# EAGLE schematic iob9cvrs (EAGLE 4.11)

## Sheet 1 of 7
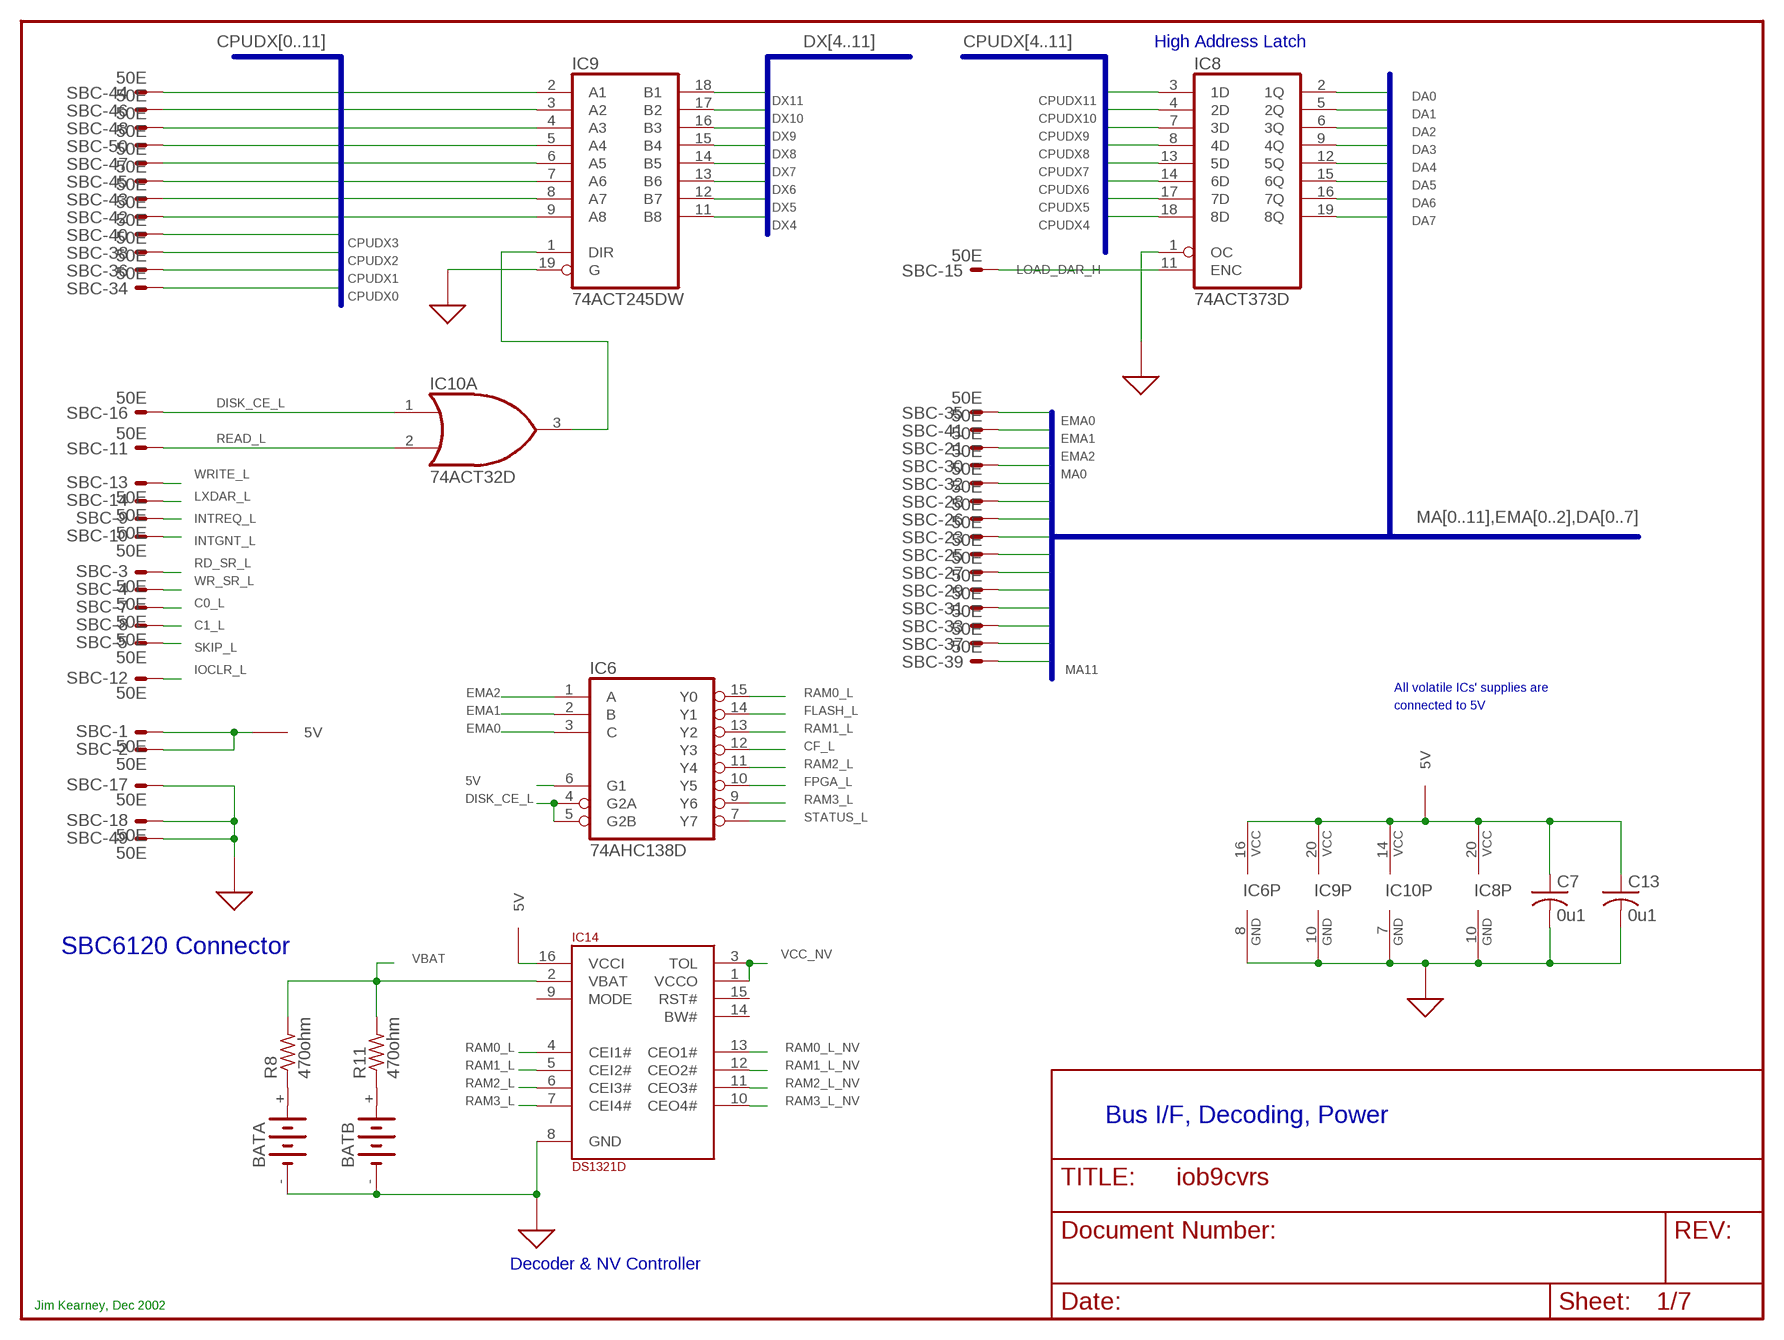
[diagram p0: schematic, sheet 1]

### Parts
BATA  CR2032HOLDER  [CR2032HOLDER]
BATB  CR2032HOLDER  [CR2032HOLDER]
C7  0u1  C-USC0805  [C0805]
C13  0u1  C-USC0805  [C0805]
IC6  74AHC138D  74LS138D  [SO16]
IC8  74ACT373D  74LS373DW  [SO20W]
IC9  74ACT245DW  74LS245DW  [SO20W]
IC10  74ACT32D  74LS32D  [SO14]
IC14  DS1321D  [SO16]
R8  470ohm  R-US_M0805  [M0805]
R11  470ohm  R-US_M0805  [M0805]
SBC  50E  ML50E  [ML50]

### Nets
5V [power]: C7.1 C13.1 IC6.6(G1) IC6.16(VCC) IC8.20(VCC) IC9.20(VCC) IC10.14(P:VCC) IC14.16(VCCI) SBC.1 SBC.2 ; also sheet 2,3,4,5,6
C0_L: SBC.7 ; also sheet 4
C1_L: SBC.8 ; also sheet 4
CF_L: IC6.12(Y3) ; also sheet 3
CPUDX0: SBC.34 ; also sheet 4,5
CPUDX1: SBC.36 ; also sheet 4,5
CPUDX2: SBC.38 ; also sheet 4,5
CPUDX3: SBC.40 ; also sheet 4,5
CPUDX4: IC8.18(8D) IC9.9(A8) SBC.42 ; also sheet 3,5
CPUDX5: IC8.17(7D) IC9.8(A7) SBC.43 ; also sheet 3,5
CPUDX6: IC8.14(6D) IC9.7(A6) SBC.45 ; also sheet 3,5
CPUDX7: IC8.13(5D) IC9.6(A5) SBC.47 ; also sheet 3,5
CPUDX8: IC8.8(4D) IC9.5(A4) SBC.50 ; also sheet 3,5
CPUDX9: IC8.7(3D) IC9.4(A3) SBC.48 ; also sheet 3,5
CPUDX10: IC8.4(2D) IC9.3(A2) SBC.46 ; also sheet 3,5
CPUDX11: IC8.3(1D) IC9.2(A1) SBC.44 ; also sheet 3,5
DA0: IC8.2(1Q) ; also sheet 2
DA1: IC8.5(2Q) ; also sheet 2
DA2: IC8.6(3Q) ; also sheet 2
DA3: IC8.9(4Q) ; also sheet 2
DA4: IC8.12(5Q) ; also sheet 2
DA5: IC8.15(6Q) ; also sheet 2
DA6: IC8.16(7Q) ; also sheet 2
DA7: IC8.19(8Q)
DISK_CE_L: IC6.4(G2A) IC6.5(G2B) IC10.1(A:I0) SBC.16
DX4: IC9.11(B8) ; also sheet 2,3
DX5: IC9.12(B7) ; also sheet 2,3
DX6: IC9.13(B6) ; also sheet 2,3
DX7: IC9.14(B5) ; also sheet 2,3
DX8: IC9.15(B4) ; also sheet 2,3
DX9: IC9.16(B3) ; also sheet 2,3
DX10: IC9.17(B2) ; also sheet 2,3
DX11: IC9.18(B1) ; also sheet 2,3
EMA0: IC6.3(C) SBC.35
EMA1: IC6.2(B) SBC.41
EMA2: IC6.1(A) SBC.21
FLASH_L: IC6.14(Y1) ; also sheet 2
FPGA_L: IC6.10(Y5) ; also sheet 3
GND [gnd]: BATA.- BATB.- C7.2 C13.2 IC6.8(GND) IC8.1(OC) IC8.10(GND) IC9.10(GND) IC9.19(G) IC10.7(P:GND) IC14.8(GND) SBC.17 SBC.18 SBC.49 ; also sheet 2,3,4,5,6,7
INTGNT_L: SBC.10 ; also sheet 4
INTREQ_L: SBC.9 ; also sheet 4
IOCLR_L: SBC.12 ; also sheet 2,4
LOAD_DAR_H: IC8.11(ENC) SBC.15
LXDAR_L: SBC.14 ; also sheet 4
MA0: SBC.30 ; also sheet 2
MA1: SBC.32 ; also sheet 2
MA2: SBC.28 ; also sheet 2
MA3: SBC.26 ; also sheet 2
MA4: SBC.23 ; also sheet 2
MA5: SBC.25 ; also sheet 2
MA6: SBC.27 ; also sheet 2
MA7: SBC.29 ; also sheet 2
MA8: SBC.31 ; also sheet 2
MA9: SBC.33 ; also sheet 2,3
MA10: SBC.37 ; also sheet 2,3
MA11: SBC.39 ; also sheet 2,3
N$2: BATA.+ R8.1
N$11: BATB.+ R11.1
N$91: IC9.1(DIR) IC10.3(A:O)
RAM0_L: IC6.15(Y0) IC14.4(CEI1#)
RAM0_L_NV: IC14.13(CEO1#) ; also sheet 2
RAM1_L: IC6.13(Y2) IC14.5(CEI2#)
RAM1_L_NV: IC14.12(CEO2#) ; also sheet 2
RAM2_L: IC6.11(Y4) IC14.6(CEI3#)
RAM2_L_NV: IC14.11(CEO3#) ; also sheet 2
RAM3_L: IC6.9(Y6) IC14.7(CEI4#)
RAM3_L_NV: IC14.10(CEO4#) ; also sheet 2
RD_SR_L: SBC.3 ; also sheet 4
READ_L: IC10.2(A:I1) SBC.11 ; also sheet 2,3,4
SKIP_L: SBC.5 ; also sheet 4
STATUS_L: IC6.7(Y7) ; also sheet 3
VBAT: IC14.2(VBAT) R8.2 R11.2 ; also sheet 6
VCC_NV [power]: IC14.1(VCCO) IC14.3(TOL) ; also sheet 2
WR_SR_L: SBC.4 ; also sheet 4
WRITE_L: SBC.13 ; also sheet 2,3,4
Unconnected: IC14.9(MODE) IC14.14(BW#) IC14.15(RST#) SBC.6 SBC.19 SBC.20 SBC.22 SBC.24

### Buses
DX[4..11]
MA[0..11],EMA[0..2],DA[0..7]
CPUDX[0..11]
CPUDX[4..11]

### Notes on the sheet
- High Address Latch
- All volatile ICs' supplies are
- connected to 5V
- SBC6120 Connector
- Bus I/F, Decoding, Power
- Decoder & NV Controller
- Jim Kearney, Dec 2002

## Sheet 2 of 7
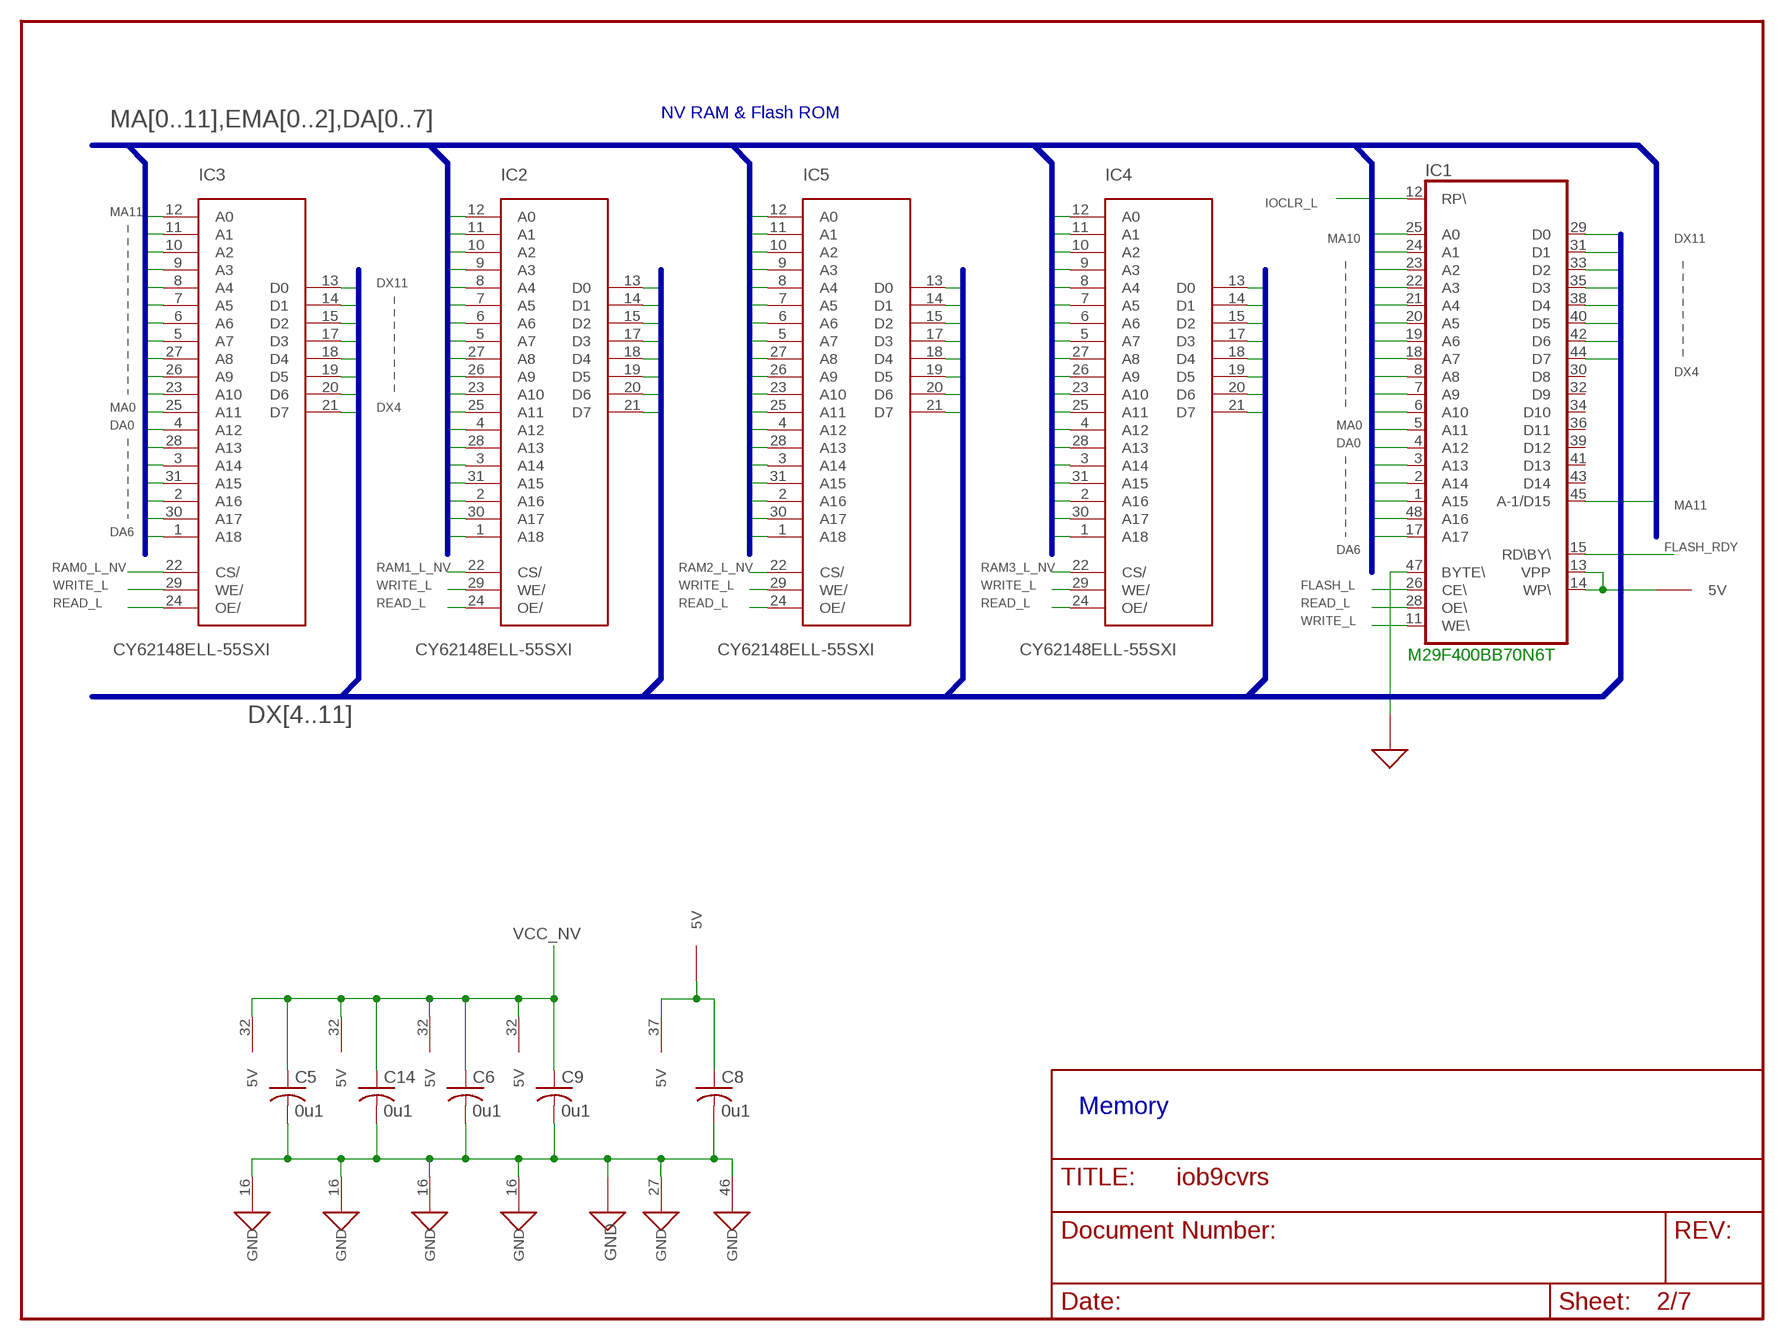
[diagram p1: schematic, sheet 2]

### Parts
C5  0u1  C-USC0805  [C0805]
C6  0u1  C-USC0805  [C0805]
C8  0u1  C-USC0805  [C0805]
C9  0u1  C-USC0805  [C0805]
C14  0u1  C-USC0805  [C0805]
IC1  M29F400BB70N6T  LH28F400  [TSOP48]
IC2  CY62148ELL-55SXI  TC554001AF  [SOP32]
IC3  CY62148ELL-55SXI  TC554001AF  [SOP32]
IC4  CY62148ELL-55SXI  TC554001AF  [SOP32]
IC5  CY62148ELL-55SXI  TC554001AF  [SOP32]

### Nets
5V [power]: C8.1 IC1.13(VPP) IC1.14(WP\) IC1.37(5V) ; also sheet 1,3,4,5,6
DA0: IC1.5(A11) IC2.4(A12) IC3.4(A12) IC4.4(A12) IC5.4(A12) ; also sheet 1
DA1: IC1.4(A12) IC2.28(A13) IC3.28(A13) IC4.28(A13) IC5.28(A13) ; also sheet 1
DA2: IC1.3(A13) IC2.3(A14) IC3.3(A14) IC4.3(A14) IC5.3(A14) ; also sheet 1
DA3: IC1.2(A14) IC2.31(A15) IC3.31(A15) IC4.31(A15) IC5.31(A15) ; also sheet 1
DA4: IC1.1(A15) IC2.2(A16) IC3.2(A16) IC4.2(A16) IC5.2(A16) ; also sheet 1
DA5: IC1.48(A16) IC2.30(A17) IC3.30(A17) IC4.30(A17) IC5.30(A17) ; also sheet 1
DA6: IC1.17(A17) IC2.1(A18) IC3.1(A18) IC4.1(A18) IC5.1(A18) ; also sheet 1
DX4: IC1.44(D7) IC2.21(D7) IC3.21(D7) IC4.21(D7) IC5.21(D7) ; also sheet 1,3
DX5: IC1.42(D6) IC2.20(D6) IC3.20(D6) IC4.20(D6) IC5.20(D6) ; also sheet 1,3
DX6: IC1.40(D5) IC2.19(D5) IC3.19(D5) IC4.19(D5) IC5.19(D5) ; also sheet 1,3
DX7: IC1.38(D4) IC2.18(D4) IC3.18(D4) IC4.18(D4) IC5.18(D4) ; also sheet 1,3
DX8: IC1.35(D3) IC2.17(D3) IC3.17(D3) IC4.17(D3) IC5.17(D3) ; also sheet 1,3
DX9: IC1.33(D2) IC2.15(D2) IC3.15(D2) IC4.15(D2) IC5.15(D2) ; also sheet 1,3
DX10: IC1.31(D1) IC2.14(D1) IC3.14(D1) IC4.14(D1) IC5.14(D1) ; also sheet 1,3
DX11: IC1.29(D0) IC2.13(D0) IC3.13(D0) IC4.13(D0) IC5.13(D0) ; also sheet 1,3
FLASH_L: IC1.26(CE\) ; also sheet 1
FLASH_RDY: IC1.15(RD\BY\) ; also sheet 3
GND [gnd]: C5.2 C6.2 C8.2 C9.2 C14.2 IC1.27(GND) IC1.46(GND) IC1.47(BYTE\) IC2.16(GND) IC3.16(GND) IC4.16(GND) IC5.16(GND) ; also sheet 1,3,4,5,6,7
IOCLR_L: IC1.12(RP\) ; also sheet 1,4
MA0: IC1.6(A10) IC2.25(A11) IC3.25(A11) IC4.25(A11) IC5.25(A11) ; also sheet 1
MA1: IC1.7(A9) IC2.23(A10) IC3.23(A10) IC4.23(A10) IC5.23(A10) ; also sheet 1
MA2: IC1.8(A8) IC2.26(A9) IC3.26(A9) IC4.26(A9) IC5.26(A9) ; also sheet 1
MA3: IC1.18(A7) IC2.27(A8) IC3.27(A8) IC4.27(A8) IC5.27(A8) ; also sheet 1
MA4: IC1.19(A6) IC2.5(A7) IC3.5(A7) IC4.5(A7) IC5.5(A7) ; also sheet 1
MA5: IC1.20(A5) IC2.6(A6) IC3.6(A6) IC4.6(A6) IC5.6(A6) ; also sheet 1
MA6: IC1.21(A4) IC2.7(A5) IC3.7(A5) IC4.7(A5) IC5.7(A5) ; also sheet 1
MA7: IC1.22(A3) IC2.8(A4) IC3.8(A4) IC4.8(A4) IC5.8(A4) ; also sheet 1
MA8: IC1.23(A2) IC2.9(A3) IC3.9(A3) IC4.9(A3) IC5.9(A3) ; also sheet 1
MA9: IC1.24(A1) IC2.10(A2) IC3.10(A2) IC4.10(A2) IC5.10(A2) ; also sheet 1,3
MA10: IC1.25(A0) IC2.11(A1) IC3.11(A1) IC4.11(A1) IC5.11(A1) ; also sheet 1,3
MA11: IC1.45(A-1/D15) IC2.12(A0) IC3.12(A0) IC4.12(A0) IC5.12(A0) ; also sheet 1,3
RAM0_L_NV: IC3.22(CS/) ; also sheet 1
RAM1_L_NV: IC2.22(CS/) ; also sheet 1
RAM2_L_NV: IC5.22(CS/) ; also sheet 1
RAM3_L_NV: IC4.22(CS/) ; also sheet 1
READ_L: IC1.28(OE\) IC2.24(OE/) IC3.24(OE/) IC4.24(OE/) IC5.24(OE/) ; also sheet 1,3,4
VCC_NV [power]: C5.1 C6.1 C9.1 C14.1 IC2.32(5V) IC3.32(5V) IC4.32(5V) IC5.32(5V) ; also sheet 1
WRITE_L: IC1.11(WE\) IC2.29(WE/) IC3.29(WE/) IC4.29(WE/) IC5.29(WE/) ; also sheet 1,3,4
Unconnected: IC1.30(D8) IC1.32(D9) IC1.34(D10) IC1.36(D11) IC1.39(D12) IC1.41(D13) IC1.43(D14)

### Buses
MA[0..11],EMA[0..2],DA[0..7]
DX[4..11]

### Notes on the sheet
- NV RAM & Flash ROM
- M29F400BB70N6T
- Memory

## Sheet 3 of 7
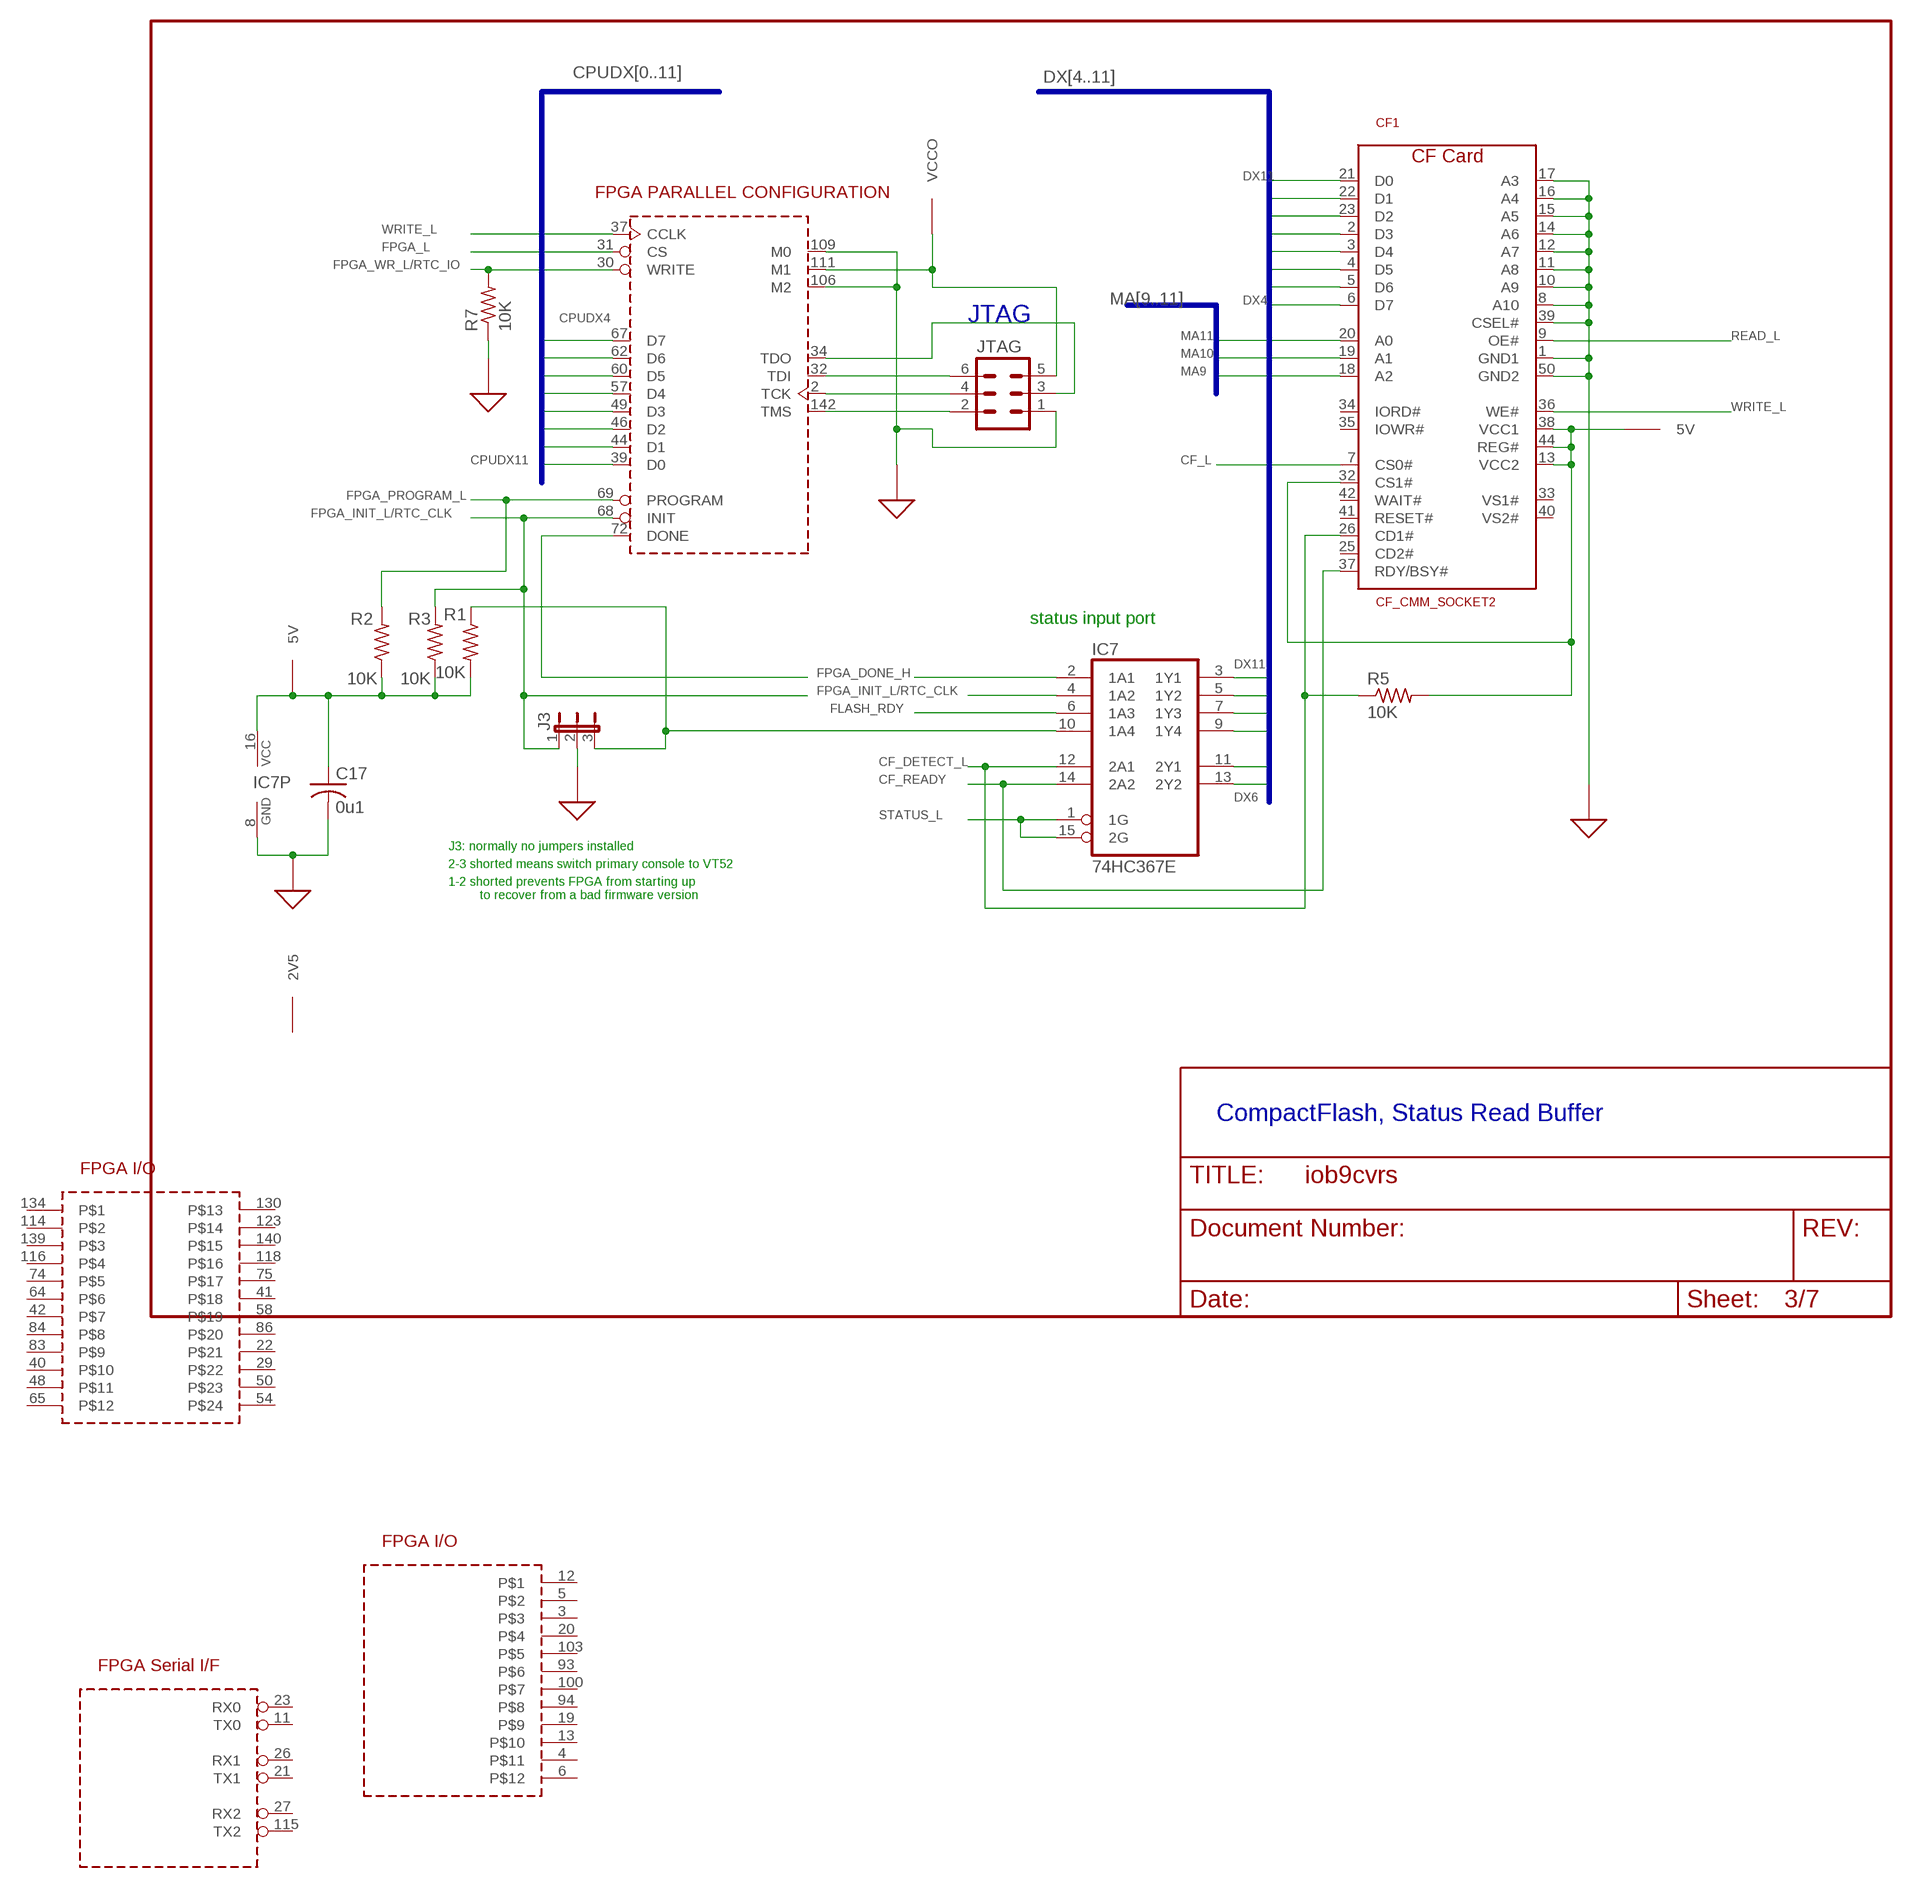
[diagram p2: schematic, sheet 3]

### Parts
C17  0u1  C-USC0805  [C0805]
CF1  CF_CMM_SOCKET2  [CF_SOCKET2_SMT]
IC7  74HC367E  74HCT367E  [SOP16]
IC12  XC2S100-5TQG144C  XC2S30-IOB1-5TQ144  [TQFP144]
J3  JP2E  [JP2]
JTAG  MA03-2  [MA03-2]
R1  10K  R-US_M0805  [M0805]
R2  10K  R-US_M0805  [M0805]
R3  10K  R-US_M0805  [M0805]
R5  10K  R-US_R0805  [R0805]
R7  10K  R-US_M0805  [M0805]

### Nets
5V [power]: C17.1 CF1.13(VCC2) CF1.32(CS1#) CF1.38(VCC1) CF1.44(REG#) IC7.16(VCC) R1.2 R2.1 R3.1 R5.2 ; also sheet 1,2,4,5,6
CF_DETECT_L: CF1.26(CD1#) IC7.12(2A1) R5.1
CF_L: CF1.7(CS0#) ; also sheet 1
CF_READY: CF1.37(RDY/BSY#) IC7.14(2A2)
CPUDX4: IC12.67(D7) ; also sheet 1,5
CPUDX5: IC12.62(D6) ; also sheet 1,5
CPUDX6: IC12.60(D5) ; also sheet 1,5
CPUDX7: IC12.57(D4) ; also sheet 1,5
CPUDX8: IC12.49(D3) ; also sheet 1,5
CPUDX9: IC12.46(D2) ; also sheet 1,5
CPUDX10: IC12.44(D1) ; also sheet 1,5
CPUDX11: IC12.39(D0) ; also sheet 1,5
DX4: CF1.6(D7) ; also sheet 1,2
DX5: CF1.5(D6) ; also sheet 1,2
DX6: CF1.4(D5) IC7.13(2Y2) ; also sheet 1,2
DX7: CF1.3(D4) IC7.11(2Y1) ; also sheet 1,2
DX8: CF1.2(D3) IC7.9(1Y4) ; also sheet 1,2
DX9: CF1.23(D2) IC7.7(1Y3) ; also sheet 1,2
DX10: CF1.22(D1) IC7.5(1Y2) ; also sheet 1,2
DX11: CF1.21(D0) IC7.3(1Y1) ; also sheet 1,2
FLASH_RDY: IC7.6(1A3) ; also sheet 2
FPGA_DONE_H: IC7.2(1A1) IC12.72(DONE)
FPGA_INIT_L/RTC_CLK: IC7.4(1A2) IC12.68(INIT) J3.1 R3.2 ; also sheet 6
FPGA_L: IC12.31(CS) ; also sheet 1
FPGA_PROGRAM_L: IC12.69(PROGRAM) R2.2 ; also sheet 4
FPGA_WR_L/RTC_IO: IC12.30(WRITE) R7.2 ; also sheet 6
GND [gnd]: C17.2 CF1.1(GND1) CF1.8(A10) CF1.10(A9) CF1.11(A8) CF1.12(A7) CF1.14(A6) CF1.15(A5) CF1.16(A4) CF1.17(A3) CF1.39(CSEL#) CF1.50(GND2) IC7.8(GND) IC12.106(M2) IC12.109(M0) J3.2 JTAG.1 R7.1 ; also sheet 1,2,4,5,6,7
MA9: CF1.18(A2) ; also sheet 1,2
MA10: CF1.19(A1) ; also sheet 1,2
MA11: CF1.20(A0) ; also sheet 1,2
N$3: IC7.10(1A4) J3.3 R1.1
READ_L: CF1.9(OE#) ; also sheet 1,2,4
STATUS_L: IC7.1(1G) IC7.15(2G) ; also sheet 1
TCK: IC12.2(TCK) JTAG.4
TDI: IC12.32(TDI) JTAG.6
TDO: IC12.34(TDO) JTAG.3
TMS: IC12.142(TMS) JTAG.2
VCCO [power2]: IC12.111(M1) JTAG.5 ; also sheet 4
WRITE_L: CF1.36(WE#) IC12.37(CCLK) ; also sheet 1,2,4
Unconnected: CF1.25(CD2#) CF1.33(VS1#) CF1.34(IORD#) CF1.35(IOWR#) CF1.40(VS2#) CF1.41(RESET#) CF1.42(WAIT#)

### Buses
DX[4..11]
MA[9..11]
CPUDX[0..11]

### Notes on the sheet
- JTAG
- status input port
- J3: normally no jumpers installed
- 2-3 shorted means switch primary console to VT52
- 1-2 shorted prevents FPGA from starting up
- to recover from a bad firmware version
- CompactFlash, Status Read Buffer

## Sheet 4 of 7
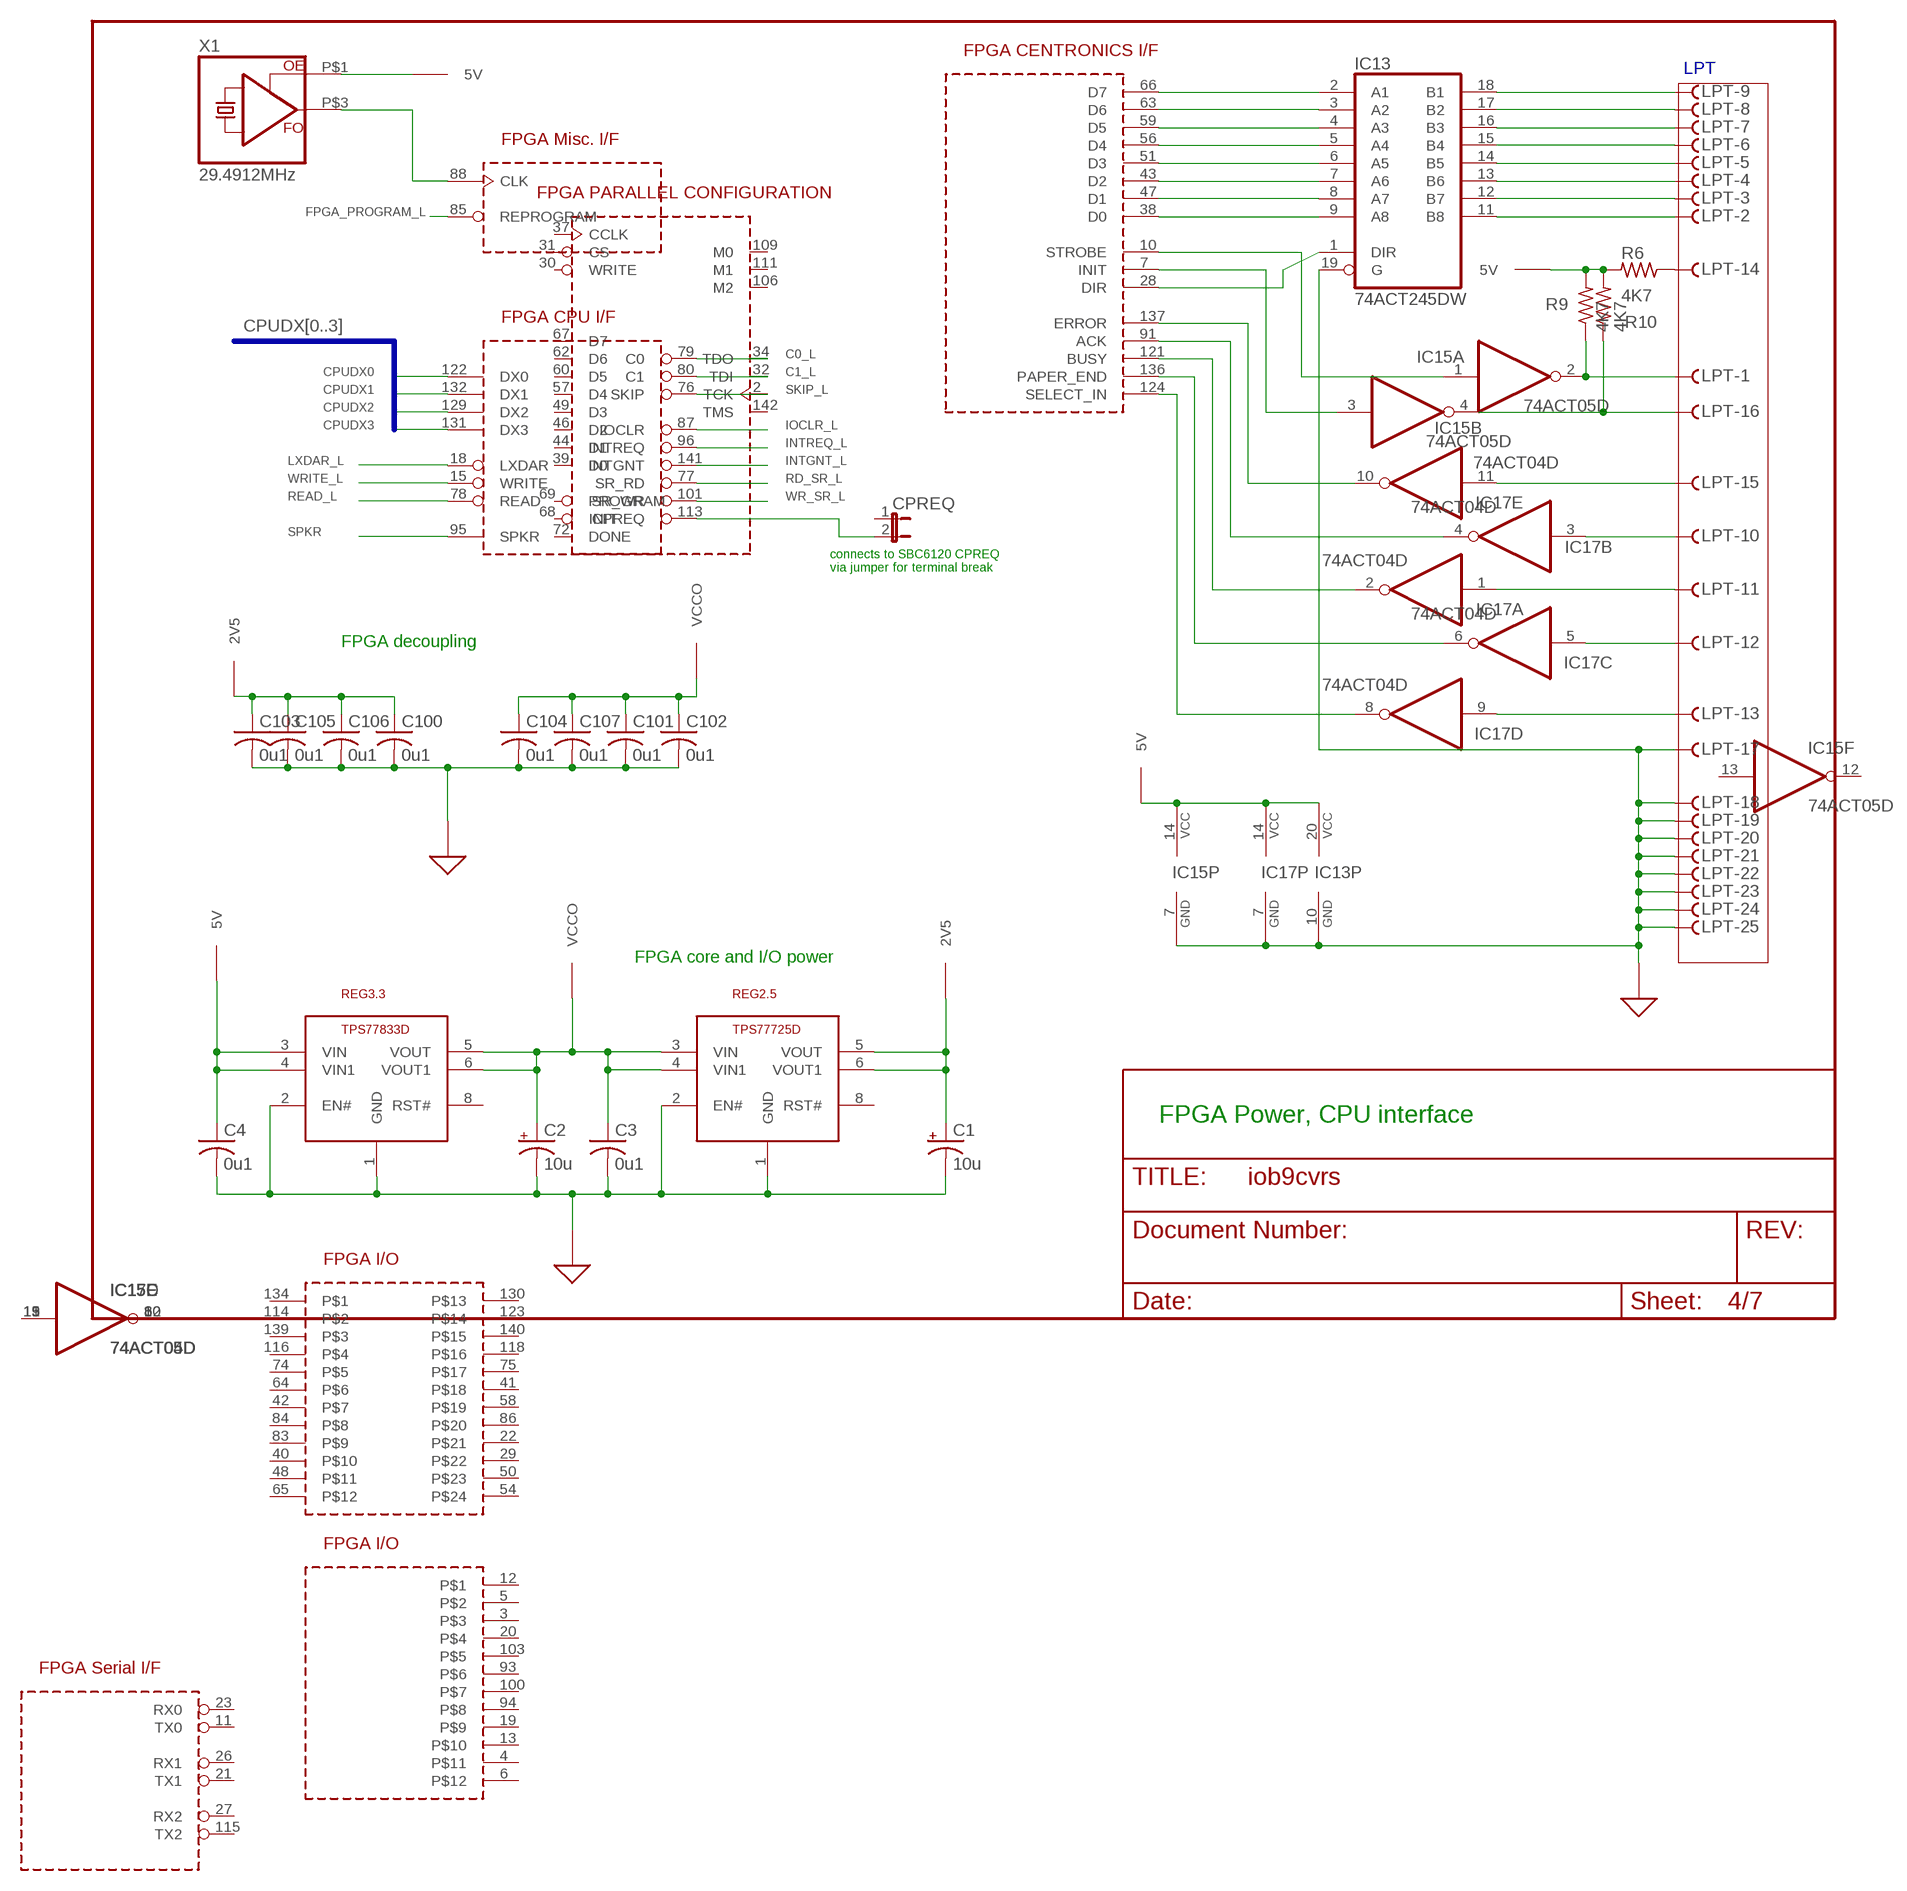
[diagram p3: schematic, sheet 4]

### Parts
C1  10u  CPOL-USD/7343-31W  [D/7343-31W]
C2  10u  CPOL-USD/7343-31W  [D/7343-31W]
C3  0u1  C-USC0805  [C0805]
C4  0u1  C-USC0805  [C0805]
C100  0u1  C-USC0805  [C0805]
C101  0u1  C-USC0805  [C0805]
C102  0u1  C-USC0805  [C0805]
C103  0u1  C-USC0805  [C0805]
C104  0u1  C-USC0805  [C0805]
C105  0u1  C-USC0805  [C0805]
C106  0u1  C-USC0805  [C0805]
C107  0u1  C-USC0805  [C0805]
CPREQ  JP1E  [JP1]
IC13  74ACT245DW  74LS245DW  [SO20W]
IC15  74ACT05D  74ALS05D  [SO14]
IC17  74ACT04D  74ALS04D  [SO14]
LPT  F25HS  [F25H]
R6  4K7  R-US_M0805  [M0805]
R9  4K7  R-US_M0805  [M0805]
R10  4K7  R-US_M0805  [M0805]
REG2.5  TPS77725D  TPS77XXXD  [SO08]
REG3.3  TPS77833D  TPS77XXXD  [SO08]
X1  29.4912MHz  OSC-OE-5V  [SG636]

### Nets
2V5 [power2]: C1.+ C100.1 C103.1 C105.1 C106.1 REG2.5.5(VOUT) REG2.5.6(VOUT1)
5V [power]: C4.1 IC13.20(VCC) IC15.14(P:VCC) IC17.14(P:VCC) R6.2 R9.2 R10.2 REG3.3.3(VIN) REG3.3.4(VIN1) X1.P$1(OE) ; also sheet 1,2,3,5,6
C0_L: IC12.79(C0) ; also sheet 1
C1_L: IC12.80(C1) ; also sheet 1
CPUDX0: IC12.122(DX0) ; also sheet 1,5
CPUDX1: IC12.132(DX1) ; also sheet 1,5
CPUDX2: IC12.129(DX2) ; also sheet 1,5
CPUDX3: IC12.131(DX3) ; also sheet 1,5
FPGA_PROGRAM_L: IC12.85(REPROGRAM) ; also sheet 3
GND [gnd]: C1.- C2.- C3.2 C4.2 C100.2 C101.2 C102.2 C103.2 C104.2 C105.2 C106.2 C107.2 IC13.10(GND) IC13.19(G) IC15.7(P:GND) IC17.7(P:GND) LPT.17 LPT.18 LPT.19 LPT.20 LPT.21 LPT.22 LPT.23 LPT.24 LPT.25 REG2.5.1(GND) REG2.5.2(EN#) REG3.3.1(GND) REG3.3.2(EN#) ; also sheet 1,2,3,5,6,7
INTGNT_L: IC12.141(INTGNT) ; also sheet 1
INTREQ_L: IC12.96(INTREQ) ; also sheet 1
IOCLR_L: IC12.87(IOCLR) ; also sheet 1,2
LXDAR_L: IC12.18(LXDAR) ; also sheet 1
N$1: IC12.66(D7) IC13.2(A1)
N$4: IC12.63(D6) IC13.3(A2)
N$5: IC12.59(D5) IC13.4(A3)
N$6: IC12.56(D4) IC13.5(A4)
N$7: IC12.88(CLK) X1.P$3(FO)
N$10: IC12.51(D3) IC13.6(A5)
N$15: IC12.43(D2) IC13.7(A6)
N$16: IC12.47(D1) IC13.8(A7)
N$17: IC12.38(D0) IC13.9(A8)
N$18: IC12.28(DIR) IC13.1(DIR)
N$19: IC12.7(INIT) IC15.3(B:I)
N$20: IC12.10(STROBE) IC15.1(A:I)
N$21: IC12.137(ERROR) IC17.10(E:O)
N$22: IC12.91(ACK) IC17.4(B:O)
N$23: IC12.121(BUSY) IC17.2(A:O)
N$24: IC12.136(PAPER_END) IC17.6(C:O)
N$25: IC12.124(SELECT_IN) IC17.8(D:O)
N$26: IC13.18(B1) LPT.9
N$27: IC13.17(B2) LPT.8
N$28: IC13.16(B3) LPT.7
N$29: IC13.15(B4) LPT.6
N$30: IC13.14(B5) LPT.5
N$31: IC13.13(B6) LPT.4
N$32: IC13.12(B7) LPT.3
N$33: IC13.11(B8) LPT.2
N$34: IC15.2(A:O) LPT.1 R9.1
N$35: IC15.4(B:O) LPT.16 R10.1
N$36: IC17.11(E:I) LPT.15
N$37: IC17.3(B:I) LPT.10
N$38: IC17.1(A:I) LPT.11
N$39: IC17.5(C:I) LPT.12
N$40: IC17.9(D:I) LPT.13
N$52: LPT.14 R6.1
N$86: CPREQ.2 IC12.113(CPREQ)
RD_SR_L: IC12.77(SR_RD) ; also sheet 1
READ_L: IC12.78(READ) ; also sheet 1,2,3
SKIP_L: IC12.76(SKIP) ; also sheet 1
SPKR: IC12.95(SPKR) ; also sheet 6
VCCO [power2]: C2.+ C3.1 C101.1 C102.1 C104.1 C107.1 REG2.5.3(VIN) REG2.5.4(VIN1) REG3.3.5(VOUT) REG3.3.6(VOUT1) ; also sheet 3
WR_SR_L: IC12.101(SR_WR) ; also sheet 1
WRITE_L: IC12.15(WRITE) ; also sheet 1,2,3
Unconnected: CPREQ.1 REG2.5.8(RST#) REG3.3.8(RST#)

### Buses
CPUDX[0..3]

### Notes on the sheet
- LPT
- connects to SBC6120 CPREQ
- via jumper for terminal break
- FPGA decoupling
- FPGA core and I/O power
- FPGA Power, CPU interface

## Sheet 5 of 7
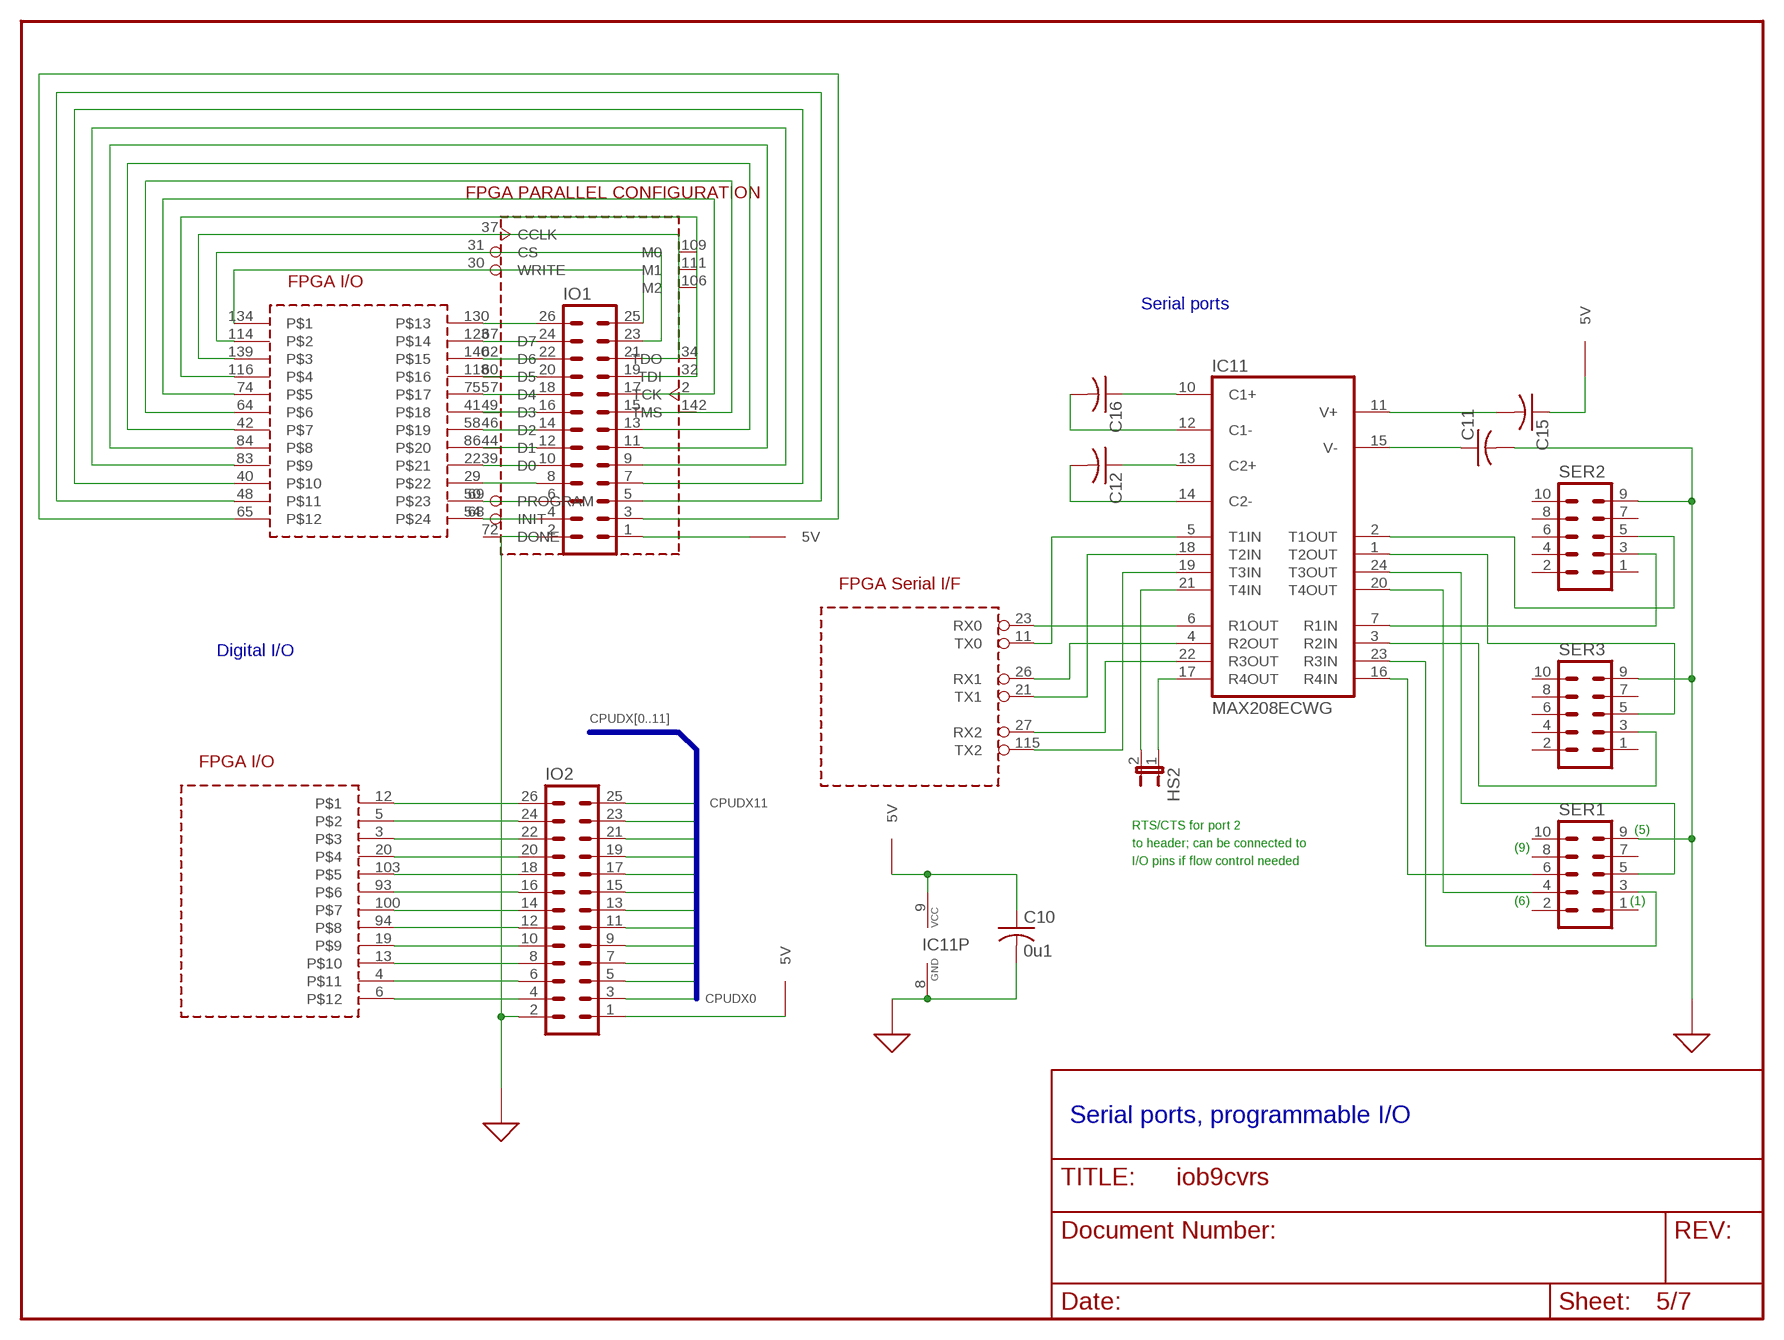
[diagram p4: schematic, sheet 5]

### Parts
C10  0u1  C-USC0805  [C0805]
C11  C-USC1206  [C1206]
C12  C-USC1206  [C1206]
C15  C-USC1206  [C1206]
C16  C-USC1206  [C1206]
HS2  JP1E  [JP1]
IC11  MAX208ECWG  [SO24L]
IO1  MA13-2  [MA13-2]
IO2  MA13-2  [MA13-2]
SER1  ML10  [ML10]
SER2  ML10  [ML10]
SER3  ML10  [ML10]

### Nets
5V [power]: C10.1 C15.1 IC11.9(VCC) IO1.1 IO2.1 ; also sheet 1,2,3,4,6
CPUDX0: IO2.3 ; also sheet 1,4
CPUDX1: IO2.5 ; also sheet 1,4
CPUDX2: IO2.7 ; also sheet 1,4
CPUDX3: IO2.9 ; also sheet 1,4
CPUDX4: IO2.11 ; also sheet 1,3
CPUDX5: IO2.13 ; also sheet 1,3
CPUDX6: IO2.15 ; also sheet 1,3
CPUDX7: IO2.17 ; also sheet 1,3
CPUDX8: IO2.19 ; also sheet 1,3
CPUDX9: IO2.21 ; also sheet 1,3
CPUDX10: IO2.23 ; also sheet 1,3
CPUDX11: IO2.25 ; also sheet 1,3
CTS2: HS2.1 IC11.17(R4OUT)
GND [gnd]: C10.2 C11.2 IC11.8(GND) IO1.2 IO2.2 SER1.9 SER2.9 SER3.9 ; also sheet 1,2,3,4,6,7
N$41: IC12.130 IO1.26
N$42: IC12.123 IO1.24
N$43: IC12.140 IO1.22
N$44: IC12.118 IO1.20
N$45: IC12.75 IO1.18
N$46: IC12.41 IO1.16
N$47: IC12.58 IO1.14
N$48: IC12.86 IO1.12
N$49: IC12.22 IO1.10
N$50: IC12.29 IO1.8
N$51: IC12.50 IO1.6
N$53: IC12.54 IO1.4
N$54: IC12.134 IO1.25
N$55: IC12.114 IO1.23
N$56: IC12.139 IO1.21
N$57: IC12.116 IO1.19
N$58: IC12.74 IO1.17
N$59: IC12.64 IO1.15
N$60: IC12.42 IO1.13
N$61: IC12.84 IO1.11
N$62: IC12.83 IO1.9
N$63: IC12.40 IO1.7
N$64: IC12.48 IO1.5
N$65: IC12.65 IO1.3
N$66: IC12.12 IO2.26
N$67: IC12.5 IO2.24
N$71: IC12.3 IO2.22
N$72: IC12.20 IO2.20
N$73: IC12.103 IO2.18
N$74: IC12.93 IO2.16
N$75: IC12.100 IO2.14
N$76: IC11.16(R4IN) SER1.6
N$77: IC12.94 IO2.12
N$78: IC12.19 IO2.10
N$79: IC12.13 IO2.8
N$80: IC12.4 IO2.6
N$81: IC12.6 IO2.4
N$92: IC11.6(R1OUT) IC12.23(RX0)
N$93: IC11.5(T1IN) IC12.11(TX0)
N$94: IC11.4(R2OUT) IC12.26(RX1)
N$95: IC11.18(T2IN) IC12.21(TX1)
N$96: IC11.22(R3OUT) IC12.27(RX2)
N$97: IC11.19(T3IN) IC12.115(TX2)
N$101: C16.1 IC11.10(C1+)
N$102: C16.2 IC11.12(C1-)
N$103: C12.1 IC11.13(C2+)
N$104: C12.2 IC11.14(C2-)
N$105: C15.2 IC11.11(V+)
N$107: C11.1 IC11.15(V-)
N$110: IC11.7(R1IN) SER2.3
N$112: IC11.3(R2IN) SER3.3
N$113: IC11.24(T3OUT) SER1.5
N$114: IC11.23(R3IN) SER1.3
RTS2: HS2.2 IC11.21(T4IN)
TX0: IC11.2(T1OUT) SER2.5
TX1: IC11.1(T2OUT) SER3.5
TX2: IC11.20(T4OUT) SER1.4
Unconnected: SER1.1 SER1.2 SER1.7 SER1.8 SER1.10 SER2.1 SER2.2 SER2.4 SER2.6 SER2.7 SER2.8 SER2.10 SER3.1 SER3.2 SER3.4 SER3.6 SER3.7 SER3.8 SER3.10

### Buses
CPUDX[0..11]

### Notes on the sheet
- Serial ports
- Digital I/O
- RTS/CTS for port 2
- (5)
- to header; can be connected to
- (9)
- I/O pins if flow control needed
- (6) | (1)
- Serial ports, programmable I/O

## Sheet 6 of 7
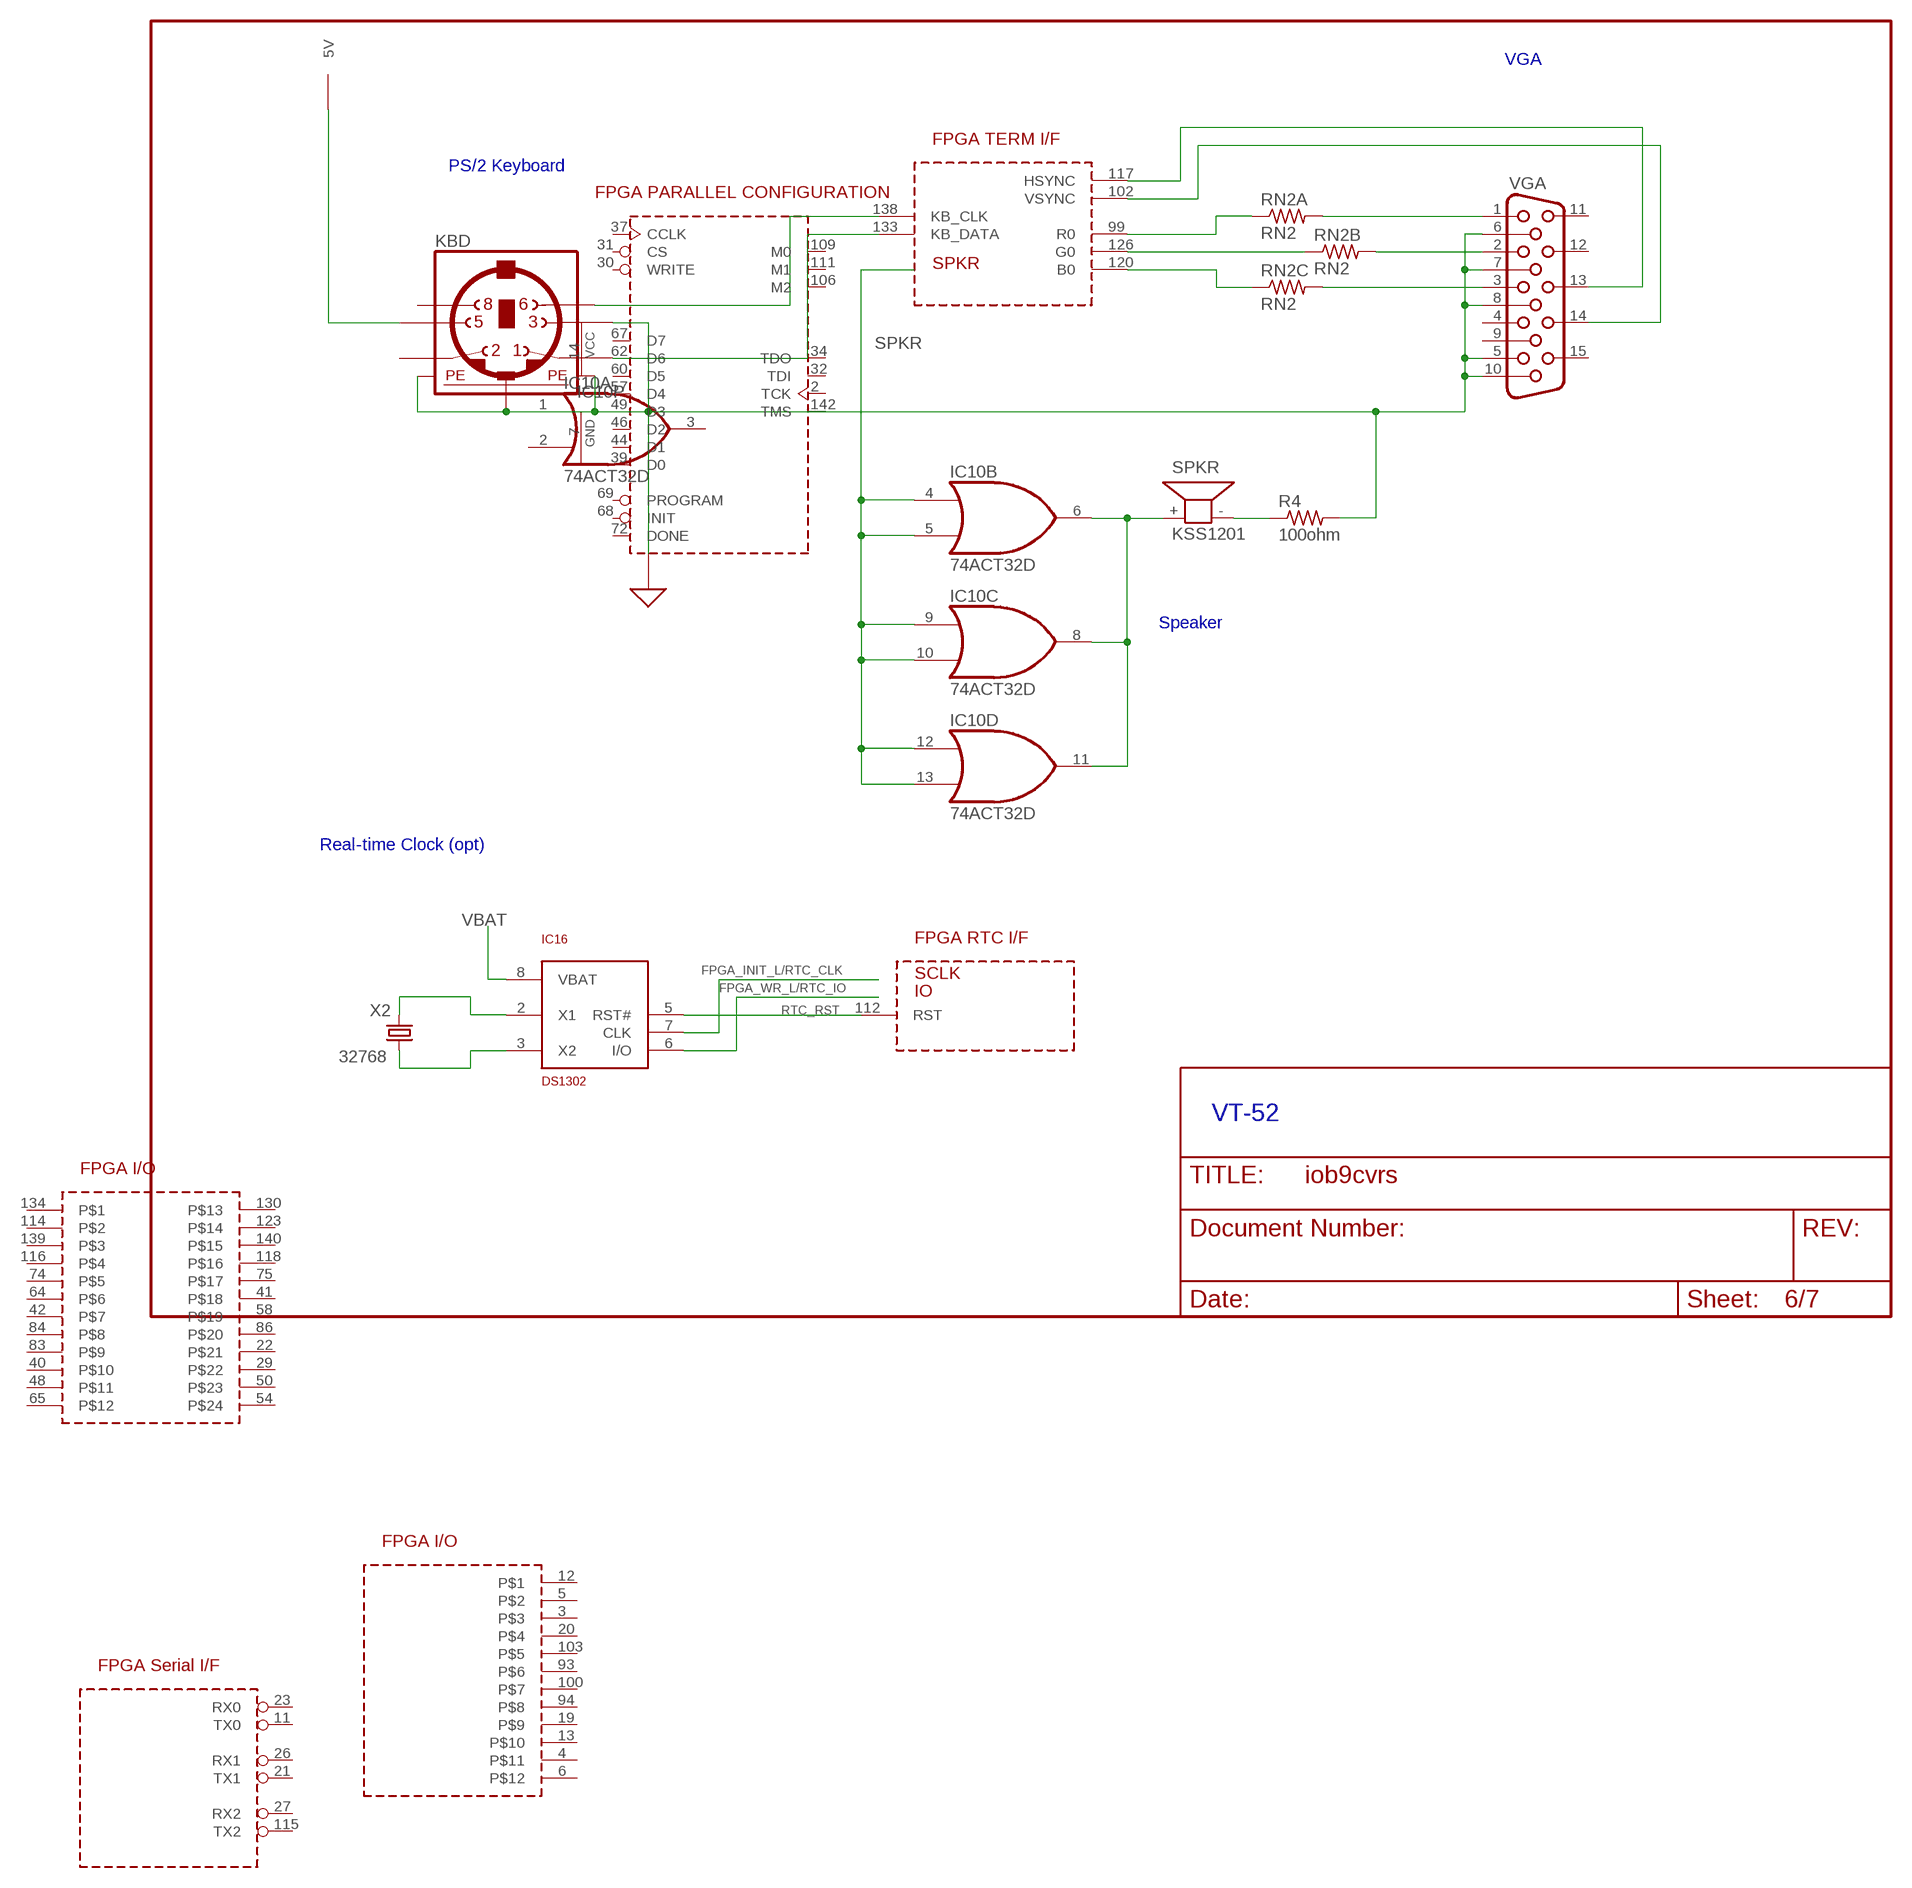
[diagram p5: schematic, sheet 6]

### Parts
IC16  DS1302  [SO08]
KBD  MINI_DIN_6  [M_DIN6]
R4  100ohm  R-US_M1206  [M1206]
RN2  RN2  RN-4-SMT  [RN-CTS-744C043]
SPKR  KSS1201  [KSS1201]
VGA  HF15H  [HDF15H]
X2  32768  CRYTALTC26H  [TC26H]

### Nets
5V [power]: KBD.5 ; also sheet 1,2,3,4,5
B0: IC12.120(B0) RN2.3
FPGA_INIT_L/RTC_CLK: IC16.7(CLK) ; also sheet 3
FPGA_WR_L/RTC_IO: IC16.6(I/O) ; also sheet 3
G0: IC12.126(G0) RN2.2
GND [gnd]: KBD.3 KBD.SH1(PE1) KBD.SH2(PE2) KBD.SH3(PE3) R4.2 VGA.5 VGA.6 VGA.7 VGA.8 VGA.10 ; also sheet 1,2,3,4,5,7
HS: IC12.117(HSYNC) VGA.13
KB_CLK: IC12.138(KB_CLK) KBD.6
KB_DATA: IC12.133(KB_DATA) KBD.1
N$8: IC16.3(X2) X2.1
N$68: RN2.8 VGA.1
N$69: RN2.7 VGA.2
N$70: RN2.6 VGA.3
N$82: IC16.2(X1) X2.2
N$106: R4.1 SPKR.-
R0: IC12.99(R0) RN2.1
RTC_RST: IC12.112(RST) IC16.5(RST#)
SPEAKER: IC10.6(B:O) IC10.8(C:O) IC10.11(D:O) SPKR.+
SPKR: IC10.4(B:I0) IC10.5(B:I1) IC10.9(C:I0) IC10.10(C:I1) IC10.12(D:I0) IC10.13(D:I1) ; also sheet 4
VBAT: IC16.8(VBAT) ; also sheet 1
VS: IC12.102(VSYNC) VGA.14
Unconnected: KBD.2 KBD.8 RN2.4 RN2.5 VGA.4 VGA.9 VGA.11 VGA.12 VGA.15

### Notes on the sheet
- VGA
- PS/2 Keyboard
- Speaker
- Real-time Clock (opt)
- VT-52

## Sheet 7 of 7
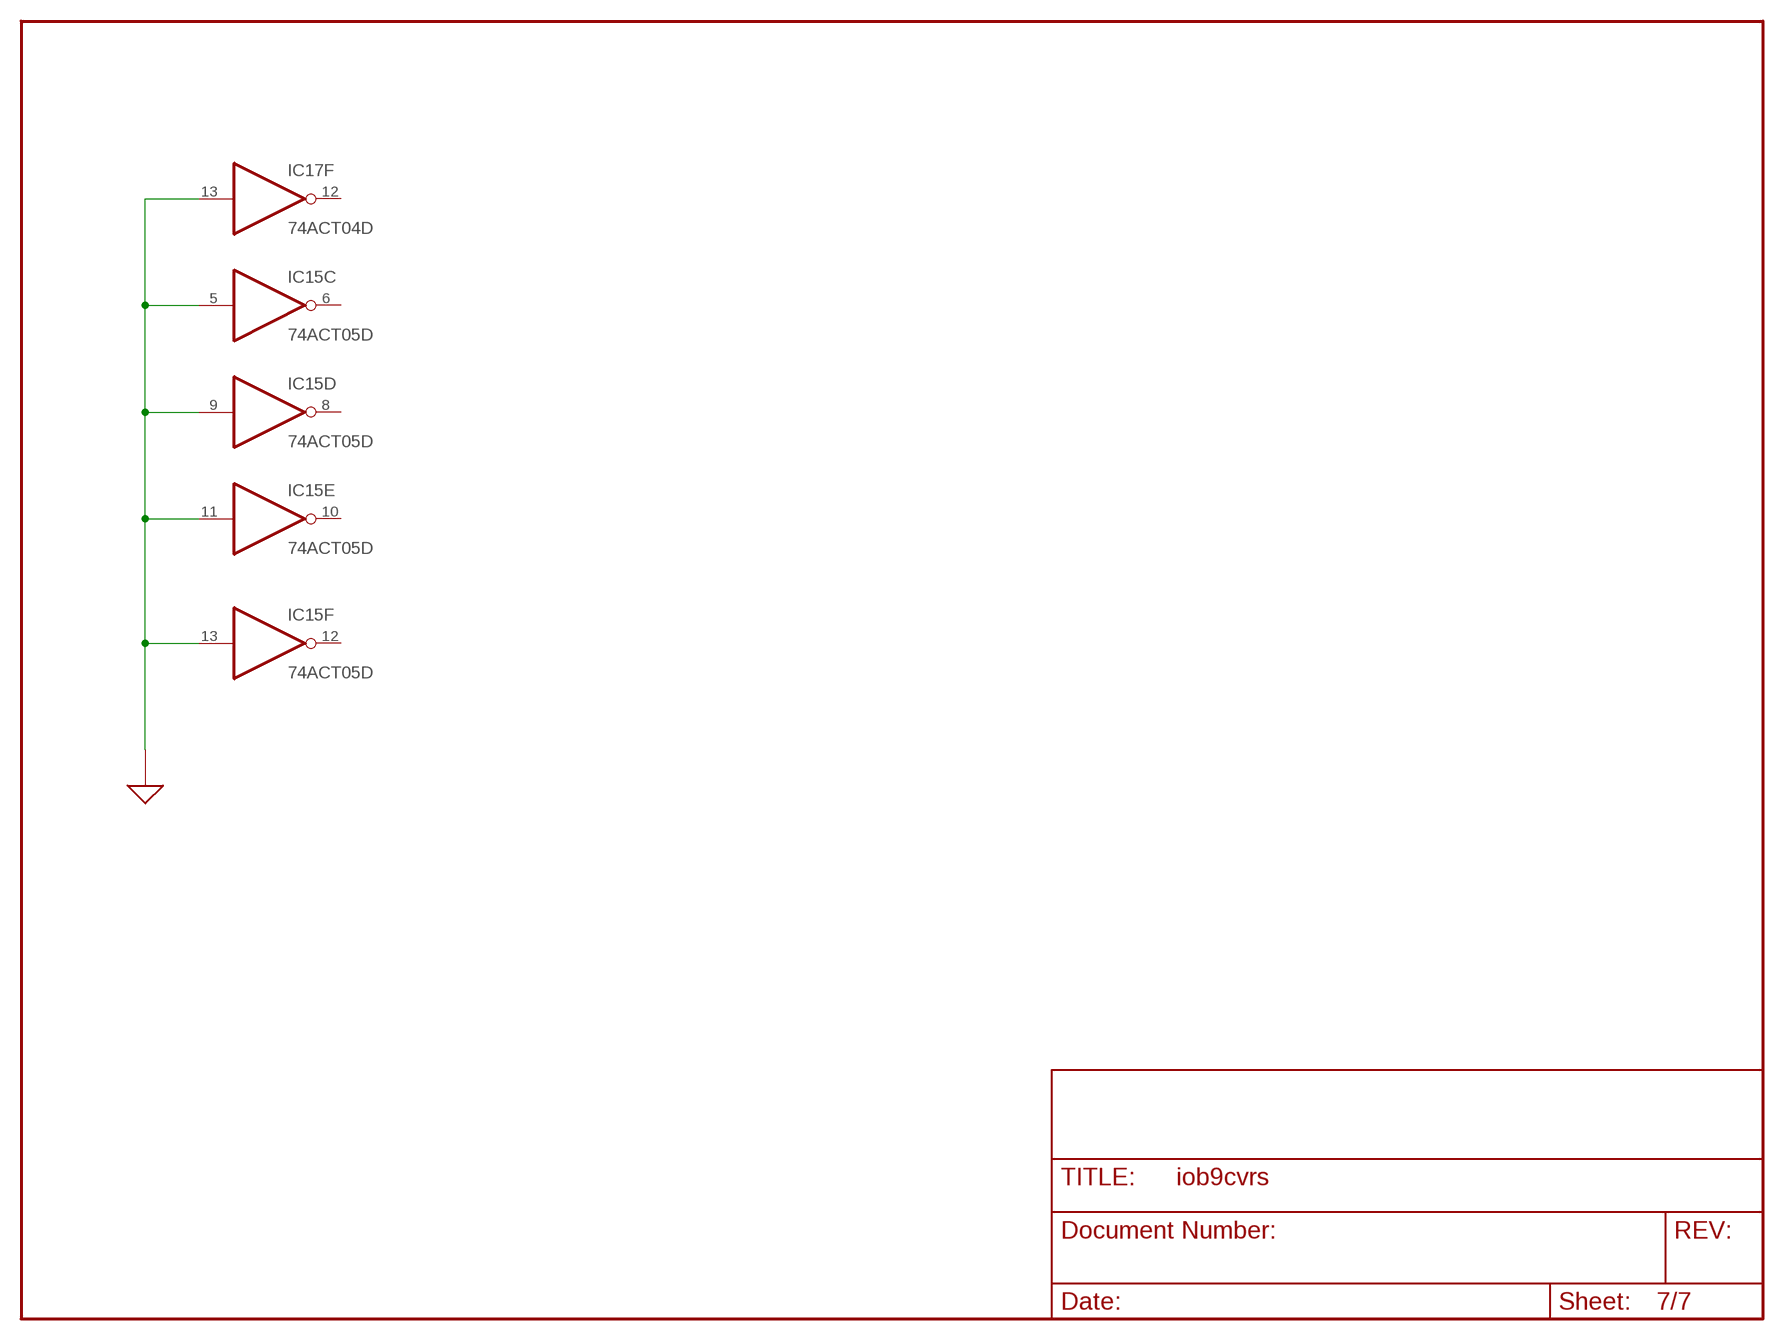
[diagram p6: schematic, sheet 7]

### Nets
GND [gnd]: IC15.5(C:I) IC15.9(D:I) IC15.11(E:I) IC15.13(F:I) IC17.13(F:I) ; also sheet 1,2,3,4,5,6
Unconnected: IC15.6(C:O) IC15.8(D:O) IC15.10(E:O) IC15.12(F:O) IC17.12(F:O)

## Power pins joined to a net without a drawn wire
2V5: IC12.9(2V5) IC12.14(2V5) IC12.24(2V5) IC12.55(2V5) IC12.82(2V5) IC12.92(2V5) IC12.97(2V5) IC12.125(2V5)
5V: IC16.1(5V) X1.P$4(5V)
GND: IC12.8(GND) IC12.17(GND) IC12.25(GND) IC12.33(GND) IC12.45(GND) IC12.52(GND) IC12.61(GND) IC12.73(GND) IC12.81(GND) IC12.89(GND) IC12.98(GND) IC12.110(GND) IC12.119(GND) IC12.128(GND) IC12.135(GND) IC12.143(GND) IC16.4(GND) X1.P$2(GND)
VCCO: IC12.1(VCCO) IC12.16(VCCO) IC12.35(VCCO) IC12.36(VCCO) IC12.53(VCCO) IC12.70(VCCO) IC12.71(VCCO) IC12.90(VCCO) IC12.107(VCCO) IC12.108(VCCO) IC12.127(VCCO) IC12.144(VCCO)

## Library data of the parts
BATA BATB = parts:CR2032
C1 C2 = rcl:CPOL-US: POLARIZED CAPACITOR, American symbol
C3-C17 C100-C107 = rcl:C-US: CAPACITOR, American symbol
CF1 = parts:CF_CMM_SOCKET2
CPREQ HS2 = jumper:JP1E: JUMPER
IC1 = parts:LH28F400
IC2-IC5 = parts:TC554001
IC6 = 74xx-us:74*138: 3-line to 8-line DECODER/DEMULTIPLEXER
IC7 = 74xx-eu:74*367: Hex BUS DRIVER, 3-state
IC8 = 74xx-us:74*373: Octal D type transparent LATCH, edge triggered
IC9 IC13 = 74xx-us:74*245: Octal BUS TRANSCEIVER, 3-state
IC10 = 74xx-us:74*32: Quad 2-input OR gate
IC11 = maxim:MAX208ECWG: RS232 TRANSEIVER
IC12 = parts:XC2S30-IOB1
IC14 = ds1321:DS1321: DS1321 Battery Monitor
IC15 = 74xx-us:74*05: Hex INVERTER, open collector
IC16 = parts:DS1302
IC17 = 74xx-us:74*04: Hex INVERTER
IO1 IO2 = con-lstb:MA13-2: PIN HEADER
J3 = jumper:JP2E: JUMPER
JTAG = con-lstb:MA03-2: PIN HEADER
KBD = mini_din:MINI_DIN_6
LPT = con-subd:F25?S: SUB-D
R1-R11 = rcl:R-US_: RESISTOR, American symbol
REG2.5 REG3.3 = parts:TPS77XXX
RN2 = parts:RN-4-SMT: 4 resistor package
SBC = con-harting-ml:ML50?E
SER1-SER3 = con-harting-ml:ML10: HARTING
SPKR = buzzer:KSS1201: SPEAKER
VGA = con-subd:HF15: SUB-D
X1 = parts:OSC-OE-5V
X2 = crystal:CRYTAL: CRYSTAL

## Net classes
1 power: width 0.254 mm, drill 0.203 mm, clearance 0.381 mm
2 gnd: width 0.254 mm, clearance 0.381 mm
3 power2: width 0.254 mm, clearance 0.381 mm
